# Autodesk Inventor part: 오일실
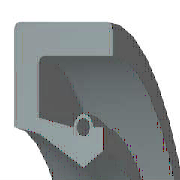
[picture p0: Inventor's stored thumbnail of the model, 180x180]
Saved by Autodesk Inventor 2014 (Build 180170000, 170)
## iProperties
IsCustomPart: 1
Created: 2015-12
Part Number: 오일실
Material: 고무
Description: 오일-실
Document SubType Name: Modeling
Standard: KS B 2804
Designer: mdu
Standards Organization: KS
Language: ko-KR
Size Designation: S - 15 30 7
Categories: <MemberInstance><Categories><Category DisplayName="샤프트 부품" InternalName="7f7aeb1f-a693-4053-b835-cee3144e0d98" Mnemonic="SHFT"><Category DisplayName="실링" Intern
Density: 0.93 g/cm^3
Appearance: 고무 - 검은색 - 버전 1.1
Mass: 1.64364 g
Surface Area: 26.6454 cm^2
Volume: 1.76736 cm^3
Author: mdu
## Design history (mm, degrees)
revolve "본체" stored, may be unused: angle "d17" = 90 deg
revolve "스프링1" stored, may be unused: angle "d18" = 90 deg
body "Solid1"
sketch "스케치1"
  geometry: L1 (0, 15)-(7, 15); L2 (7, 15)-(7, 13.75); L3 (7, 13.75)-(1.75, 13.75); L4 (0, 15)-(0, 9.6); L5 (0, 9.6)-(1.75, 9.25); L6 (1.75, 9.25)-(4.9, 7.5); L7 (4.9, 7.5)-(0, 7.5); L8 (6.3, 8.375)-(6.3, 9.6); L9 (0, 0)-(9.586, 0) reference; L10 (4.9, 7.5)-(6.3, 8.375); L11 (0, 18)-(0, -3) reference; L12 (-1.917, 0)-(11.503, 0) reference; L13 (4.2, 9.6)-(1.75, 10.09); L14 (1.75, 10.09)-(1.75, 13.75); L15 (6.3, 9.6)-(5.6, 9.6); C1 r 0.455 at (4.9, 9.6); A1 r 0.7 centre (4.9, 9.6) between (5.6, 9.6) and (4.2, 9.6)
  constraints: 26 end point, 5 horizontal alignment, 4 perpendicular, 2 centre point, 2 collinear, 2 horizontal, 2 parallel, 2 point on circle, 2 point on line, 2 vertical alignment, 1 coincident
  dimensions: "d0" = 30 diameter of L1 L9 (= SD2); "d1" = 16.75 diameter of L8.start L9 (= ABDM); "d2" = 1.25 distance of L1.end L2.end (computed from SD); "d3" = 0.91 diameter of C1 (= SPDI); "d4" = 1.4 diameter of A1 (= SPDA); "d5" = 15 diameter of L6.end L9 (= NND); "d6" = 18.5 diameter of L5.end L9 (= TKDM); "d7" = 19.2 diameter of L4.end L9 (= HLDM); "d8" = 4.9 distance from line of C1.centre L4 (= SPDST); "d9" = 6.3 distance between parallel lines of L8 L4 (= SDI); "d10" = 7 distance between parallel lines of L2 L4 (= SWDT); "d12" = 1.75 distance between parallel lines of L14 L4 (= SD)
fillet "모깎기1" dims "d11" = 0.3 (= RR)
other parameters: "SD2" = 30 [user parameter; used in 1 equation term], "SWDT" = 7 [user parameter; used in 1 equation term], "RR" = 0.3 [user parameter; used in 1 equation term], "SD" = 1.75 [user parameter; used in 2 equation terms], "NND" = 15 [user parameter; used in 1 equation term], "SPDA" = 1.4 [user parameter; used in 1 equation term], "SPDI" = 0.91 [user parameter; used in 1 equation term], "TKDM" = 18.5 [user parameter; used in 1 equation term], "HLDM" = 19.2 [user parameter; used in 1 equation term], "ABDM" = 16.75 [user parameter; used in 1 equation term], "SDI" = 6.3 [user parameter; used in 1 equation term], "SPDST" = 4.9 [user parameter; used in 1 equation term], "d13" = 0, "d14" = 0, "d15" = 0, "LAB" = 0.35 [user parameter]
